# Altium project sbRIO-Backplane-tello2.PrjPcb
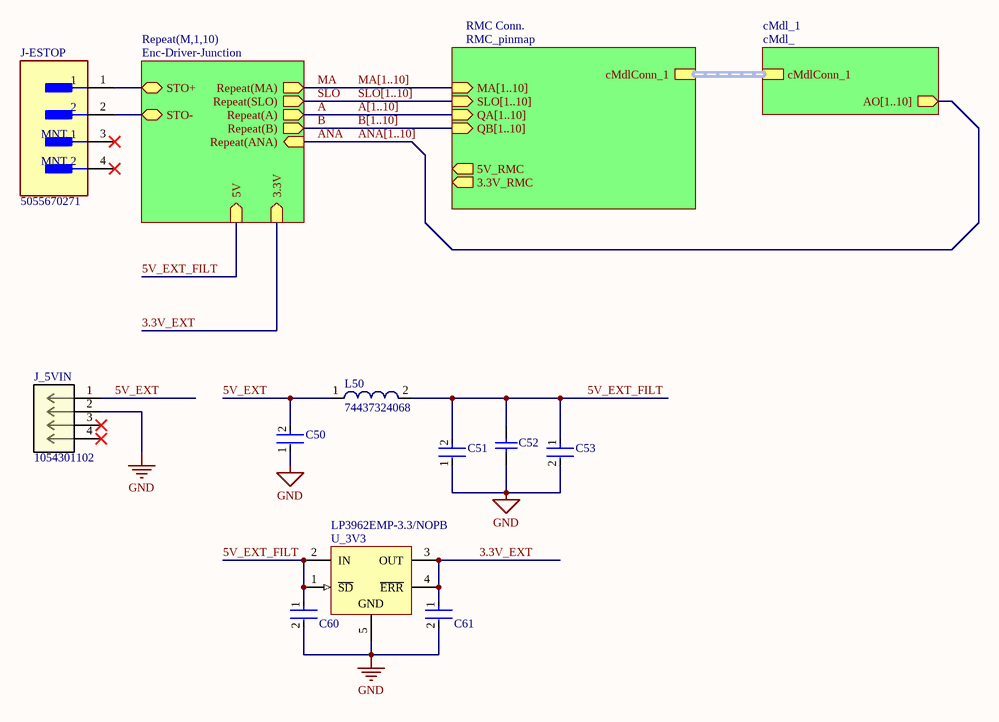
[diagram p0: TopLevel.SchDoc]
4 sheets, 123 parts. Net scope: hierarchical (ports join the sheet entries above them; power ports are global).
Board files: PCB2.PcbDoc, PCB1.PcbDoc
Sheets:
  TopLevel.SchDoc
    RMC Conn. = RMC_pinmap.SchDoc
    cMdl_1 = cMdl_.SchDoc
    M1 = Enc-Driver-Junction.SchDoc
    M2 = Enc-Driver-Junction.SchDoc
    M3 = Enc-Driver-Junction.SchDoc
    M4 = Enc-Driver-Junction.SchDoc
    M5 = Enc-Driver-Junction.SchDoc
    M6 = Enc-Driver-Junction.SchDoc
    M7 = Enc-Driver-Junction.SchDoc
    M8 = Enc-Driver-Junction.SchDoc
    M9 = Enc-Driver-Junction.SchDoc
    M10 = Enc-Driver-Junction.SchDoc

## Sheet TopLevel.SchDoc
size A; SheetNumber: 1; SheetTotal: 4

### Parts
C50  GRM155R71C104KA88D  [FP-GRM15-MFG]  (value not drawn)
C51  GRM155R71C104KA88D  [FP-GRM15-MFG]  (value not drawn)
C52  GRM31CR60J107ME39L  [CAPC3216X190X55ML30T25]  (value not drawn)
C53  0402YC103KAT2A  [FP-0402-L_1_0_1-W_0_5_0_1-MFG]  (value not drawn)
C60  C3216X5R1A686M160AC  [FP-C3216-160-0_3-MFG]  (value not drawn)
C61  C2012X5R0J336M125AC  [FP-C2012-125-0_2-IPC_C]  (value not drawn)
J-ESTOP  5055670271  [FP-5055670271-MFG]
J_5VIN  1054301102  [CON_1054301102_MOL]
L50  74437324068  [WE-LHMI 4020]
U_3V3  LP3962EMP-3.3/NOPB  [NDC0005A_M]

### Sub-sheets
cMdl_1 = cMdl_: cMdlConn_1 (harness cMdlConn_1), AO[1..10] (out)
Repeat(M,1,10) = Enc-Driver-Junction: STO- (bidir), Repeat(MA) (out), STO+ (bidir), Repeat(SLO) (out), Repeat(A) (out), Repeat(B) (out), Repeat(ANA) (in), 5V (in), 3.3V (in)
RMC Conn. = RMC_pinmap: cMdlConn_1 (harness cMdlConn_1), SLO[1..10] (in), MA[1..10] (in), QA[1..10] (in), QB[1..10] (in), 5V_RMC (out), 3.3V_RMC (out)

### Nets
GND: C50.1 C51.1 C52.1 C53.2 C60.2 C61.2 J_5VIN.2 U_3V3.5(GND)
3.3V_EXT: C61.1 U_3V3.3(OUT) U_3V3.4(~{ERR}) ; sheet Repeat(M,1,10)/3.3V
5V_EXT: C50.2 J_5VIN.1 L50.1
5V_EXT_FILT: C51.2 C52.2 C53.1 C60.1 L50.2 U_3V3.1(~{SD}) U_3V3.2(IN) ; sheet Repeat(M,1,10)/5V  [project net 5V]
STO+: J-ESTOP.1 ; sheet Repeat(M,1,10)/STO+
STO-: J-ESTOP.2 ; sheet Repeat(M,1,10)/STO-

Not connected (* = marked no-connect by the designer): J-ESTOP 3(MNT_1)* 4(MNT_2)*; J_5VIN 3* 4*

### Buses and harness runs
bus A[1..10] = sheet RMC Conn./QA[1..10]
bus ANA[1..10] = sheet cMdl_1/AO[1..10]
bus B[1..10] = sheet RMC Conn./QB[1..10]
bus MA[1..10] = sheet RMC Conn./MA[1..10]
bus SLO[1..10] = sheet RMC Conn./SLO[1..10]
harness sheet cMdl_1/cMdlConn_1 = sheet RMC Conn./cMdlConn_1

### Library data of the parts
C50 C51 = CMP-2100-03641-2: CAP CER 0.1UF 16V X7R 0402; Manufacturer: Murata; Standoff Height: 0mm; Tolerance: 10%; Voltage Rating: 16Vdc; Material: Ceramic; Capacitance: 0.10μF; Value: 0.10μF
C52 = CMP-1662-00011-2: Chip Capacitor, 100 uF, +/- 20%, 6.3 V, -55 to 85 degC, 1206 (3216 Metric), RoHS, Tape and Reel; Case\/Package: 1206; Capacitance: 100 uF; Voltage Rating (DC): 6.3 V; Type (Capacitors): X5R
C53 = CMP-2008-02797-2: General Purpose Ceramic Capacitor, 0402, 10nF, 10%, X7R, 15%, 16V; Insulation Resistance: 100GR
C60 = CMP-08246-002634-1: CAP CER 68UF 10V X5R 1206; Tolerance: 20%; Dielectric Material: Ceramic
C61 = CMP-08246-003796-1: Multilayer Ceramic Capacitors 33μF ±20% 6.3V X5R SMD 0805; Capacitance: 33uF
J-ESTOP = CMP-04776-000017-1: CONN HEADER SMD R/A 2POS 1.25MM; Manufacturer: Molex; Voltage Rating: 50V; Current Rating: 1.5A; Description: Conn Shrouded Header (4 Sides) HDR 2 POS 1.25mm Solder RA Side Entry SMD Micro-Lock™ T/R; Conn Orientation: Right Angle; Conn Gender: Male; Number Of Contacts: 2
J_5VIN = 1054301102: No Description Available; Mfr_Name: Molex Connector Corporation
L50 = CMP-1353-00039-1: SMD Power Inductor WE-LHMI, L=6.8 µH; Manufacturer: Wuerth Elektronik; Inductance: 6.8 ÂµH
U_3V3 = CMP-0062-01662-3: 1.5A Fast Ultra Low Dropout Linear Regulator, 5-pin SOT-223, Pb-Free; Manufacturer: Texas Instruments; CompType: LDO IC; PowerWise: N; PackageTopMarking: XYTT*LBEB

## Sheet RMC_pinmap.SchDoc
size A2; SheetNumber: 2; SheetTotal: 4
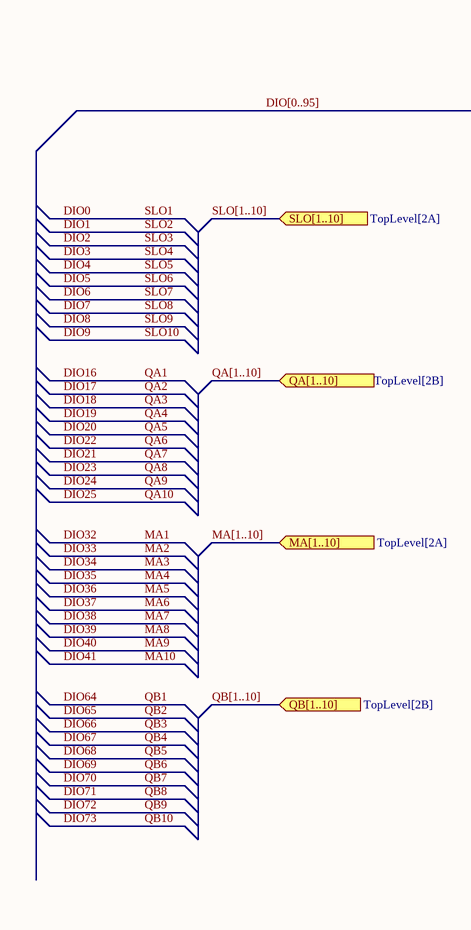
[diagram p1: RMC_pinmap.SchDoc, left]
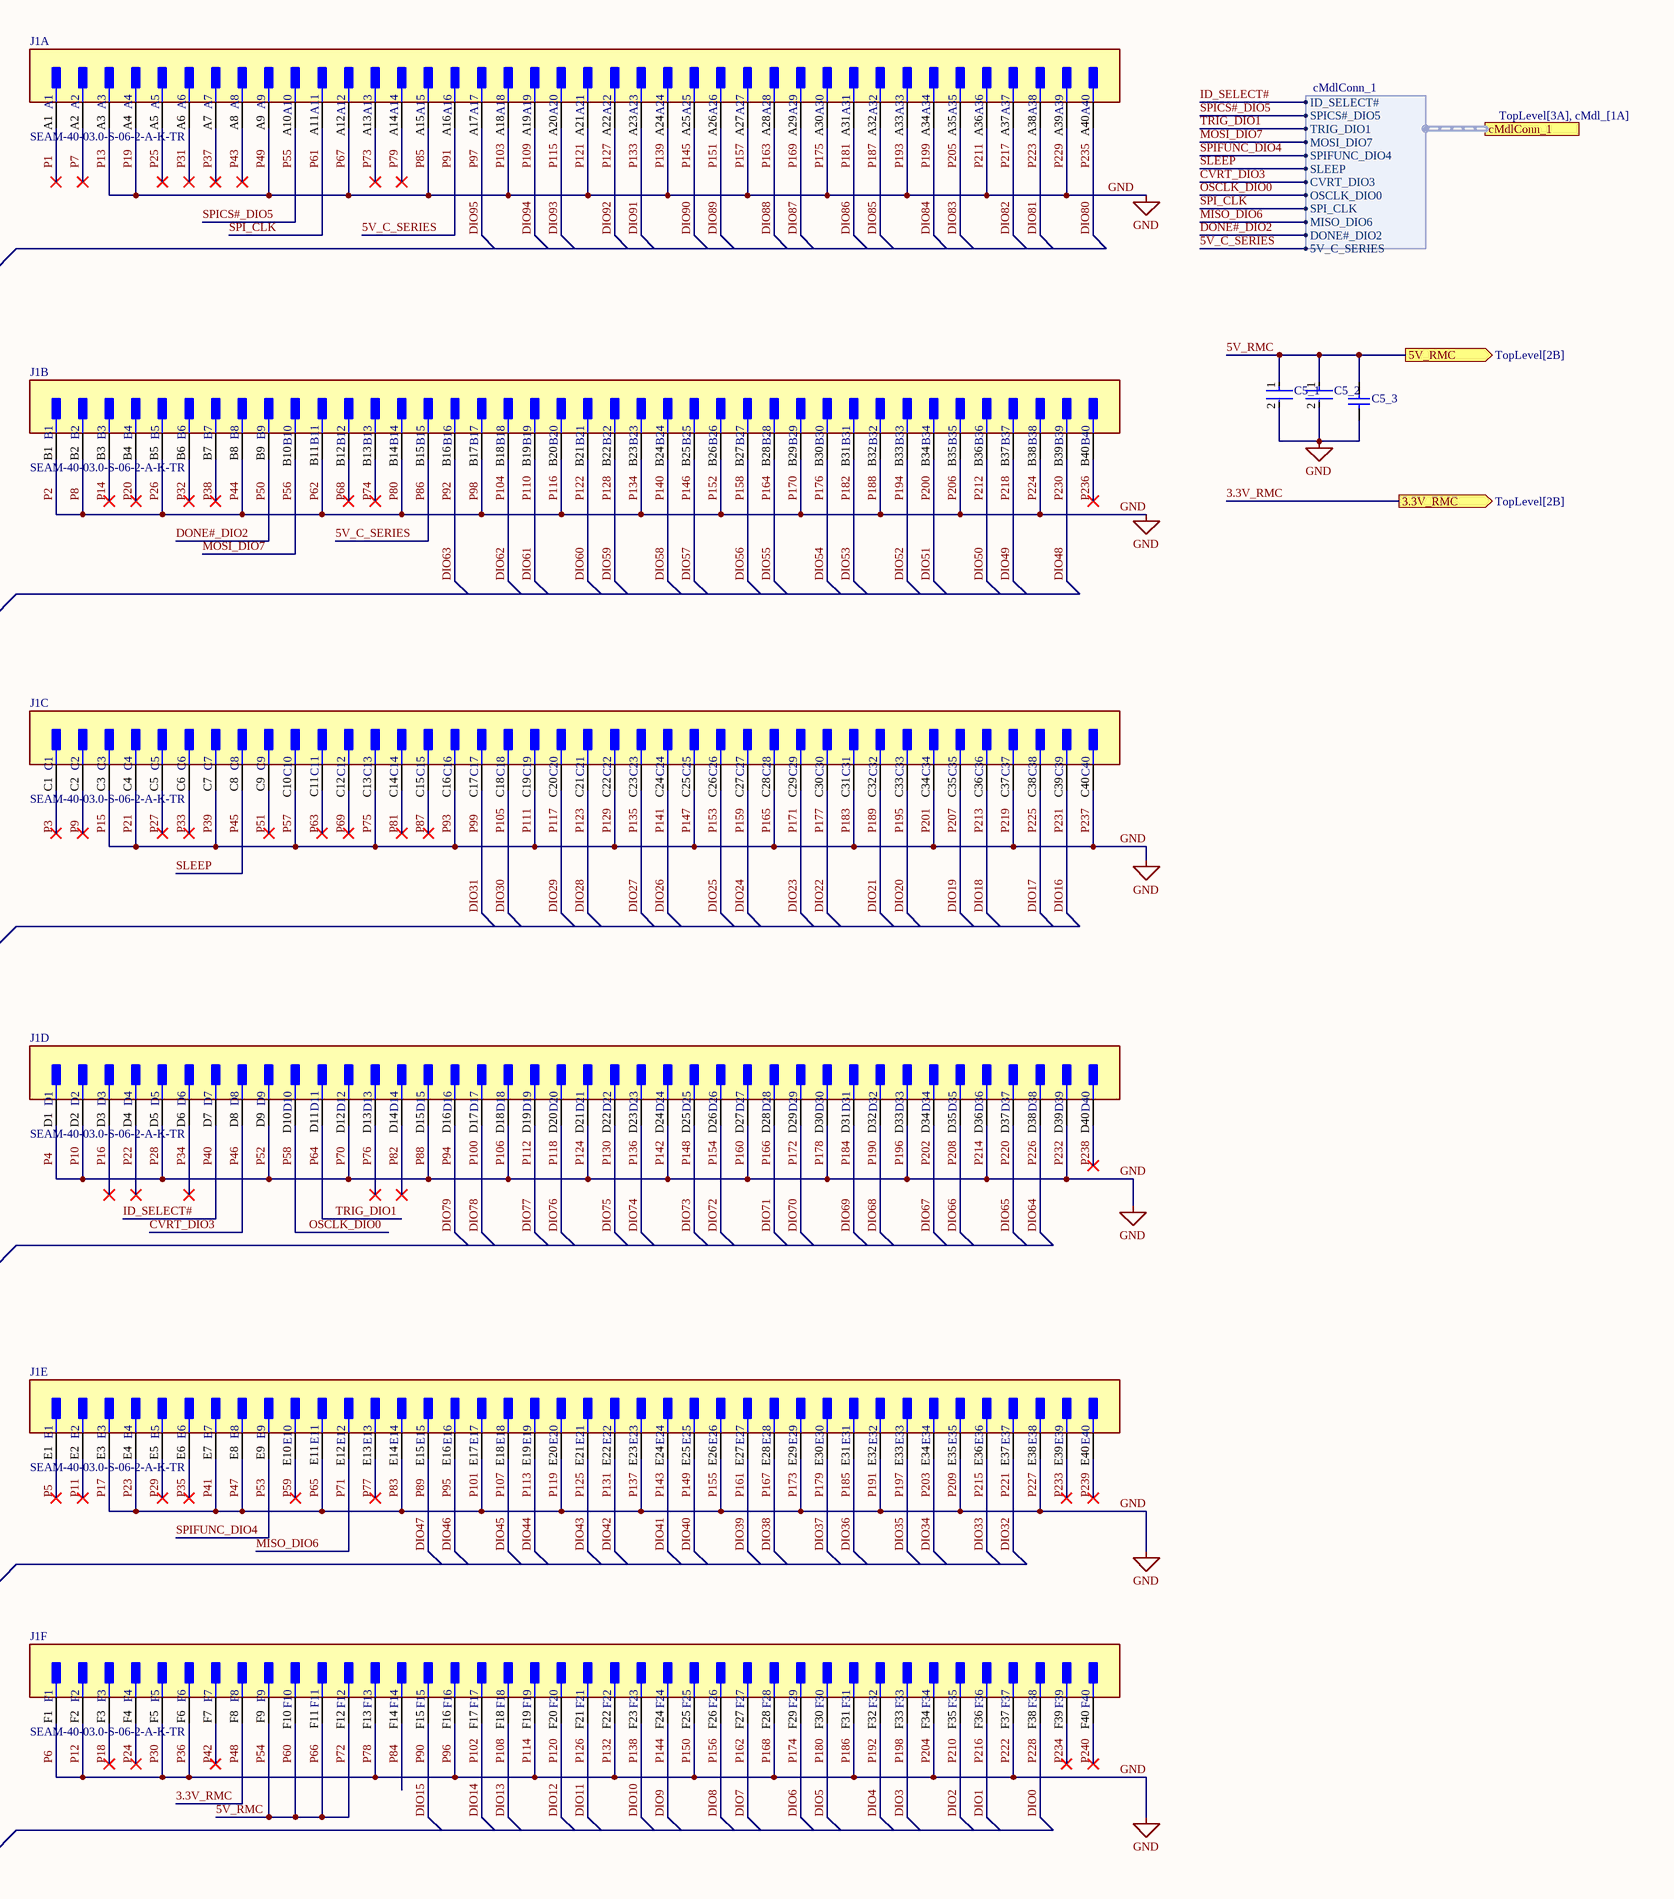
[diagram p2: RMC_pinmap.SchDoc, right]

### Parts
C5_1  C0402C105K8PACTU  [FP-C0402C105K8PACTU-MFG]  (value not drawn)
C5_2  CL05A106MP5NUNC  [FP-CL05A106MP5NUNC-MFG]  (value not drawn)
C5_3  04026D104KAT2A  [CAPC1005X56X25LL10T15]  (value not drawn)
J1  SEAM-40-03.0-S-06-2-A-K-TR  [FP-SEAM-40-03_0-S-06-2-A-MFG]  (parts A,B,C,D,E,F of 6)

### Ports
3.3V_RMC (out, see TopLevel[2B]), 5V_RMC (out, see TopLevel[2B]), cMdlConn_1 (harness cMdlConn_1, see TopLevel[3A], cMdl_[1A]), MA[1..10] (in, see TopLevel[2A]), QA[1..10] (in, see TopLevel[2B]), QB[1..10] (in, see TopLevel[2B]), SLO[1..10] (in, see TopLevel[2A])

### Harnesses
cMdlConn_1: ID_SELECT#, SPICS#_DIO5, TRIG_DIO1, MOSI_DIO7, SPIFUNC_DIO4, SLEEP, CVRT_DIO3, OSCLK_DIO0, SPI_CLK, MISO_DIO6, DONE#_DIO2, 5V_C_SERIES

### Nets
GND: C5_1.2 C5_2.2 C5_3.1 J1.A3 J1.A4 J1.A9 J1.A12 J1.A15 J1.A18 J1.A21 J1.A24 J1.A27 J1.A30 J1.A33 J1.A36 J1.A39 J1.B1 J1.B2 J1.B5 J1.B8 J1.B11 J1.B14 J1.B17 J1.B20 J1.B23 J1.B26 J1.B29 J1.B32 J1.B35 J1.B38 J1.C3 J1.C4 J1.C7 J1.C10 J1.C13 J1.C16 J1.C19 J1.C22 J1.C25 J1.C28 J1.C31 J1.C34 J1.C37 J1.C40 J1.D1 J1.D2 J1.D5 J1.D9 J1.D12 J1.D15 J1.D18 J1.D21 J1.D24 J1.D27 J1.D30 J1.D33 J1.D36 J1.D39 J1.E3 J1.E4 J1.E7 J1.E8 J1.E11 J1.E14 J1.E17 J1.E20 J1.E23 J1.E26 J1.E29 J1.E32 J1.E35 J1.E38 J1.F1 J1.F2 J1.F5 J1.F6 J1.F13 J1.F16 J1.F19 J1.F22 J1.F25 J1.F28 J1.F31 J1.F34 J1.F37  [also labelled P10, P101, P103, P106, P111, P114, P116, P119, P12, P121, P124, P129, P13, P132, P134, P137, P139, P142, P147, P15, P150, P152, P155, P157, P160, P165, P168, P17, P170, P173, P175, P178, P183, P186, P188, P19, P191, P193, P196, P2, P201, P204, P206, P209, P21, P211, P214, P219, P222, P224, P227, P229, P23, P232, P237, P26, P28, P30, P36, P39, P4, P41, P44, P47, P49, P52, P57, P6, P62, P65, P67, P70, P75, P78, P8, P80, P83, P85, P88, P93, P96, P98]
3.3V_RMC: J1.F8 ; port 3.3V_RMC  [also labelled P48]
5V_C_SERIES: J1.A16 J1.B15 ; port cMdlConn_1.5V_C_SERIES  [also labelled P86, P91]
5V_RMC: C5_1.1 C5_2.1 C5_3.2 J1.F9 J1.F10 J1.F11 J1.F12 ; port 5V_RMC  [also labelled P54, P60, P66, P72]
CVRT_DIO3: J1.D8 ; port cMdlConn_1.CVRT_DIO3  [also labelled P46]
DIO0: J1.F38  [also labelled P228, SLO1]
DIO1: J1.F36  [also labelled P216, SLO2]
DIO2: J1.F35  [also labelled P210, SLO3]
DIO3: J1.F33  [also labelled P198, SLO4]
DIO4: J1.F32  [also labelled P192, SLO5]
DIO5: J1.F30  [also labelled P180, SLO6]
DIO6: J1.F29  [also labelled P174, SLO7]
DIO7: J1.F27  [also labelled P162, SLO8]
DIO8: J1.F26  [also labelled P156, SLO9]
DIO9: J1.F24  [also labelled P144, SLO10]
DIO10: J1.F23  [also labelled P138]
DIO11: J1.F21  [also labelled P126]
DIO12: J1.F20  [also labelled P120]
DIO13: J1.F18  [also labelled P108]
DIO14: J1.F17  [also labelled P102]
DIO15: J1.F15  [also labelled P90]
DIO16: J1.C39  [also labelled P231, QA1]  [project net A]
DIO17: J1.C38  [also labelled P225, QA2]  [project net A]
DIO18: J1.C36  [also labelled P213, QA3]  [project net A]
DIO19: J1.C35  [also labelled P207, QA4]  [project net A]
DIO20: J1.C33  [also labelled P195, QA5]  [project net A]
DIO21: J1.C32  [also labelled P189, QA7]  [project net A]
DIO22: J1.C30  [also labelled P177, QA6]  [project net A]
DIO23: J1.C29  [also labelled P171, QA8]  [project net A]
DIO24: J1.C27  [also labelled P159, QA9]  [project net A]
DIO25: J1.C26  [also labelled P153, QA10]  [project net A]
DIO26: J1.C24  [also labelled P141]
DIO27: J1.C23  [also labelled P135]
DIO28: J1.C21  [also labelled P123]
DIO29: J1.C20  [also labelled P117]
DIO30: J1.C18  [also labelled P105]
DIO31: J1.C17  [also labelled P99]
DIO32: J1.E37  [also labelled MA1, P221]
DIO33: J1.E36  [also labelled MA2, P215]
DIO34: J1.E34  [also labelled MA3, P203]
DIO35: J1.E33  [also labelled MA4, P197]
DIO36: J1.E31  [also labelled MA5, P185]
DIO37: J1.E30  [also labelled MA6, P179]
DIO38: J1.E28  [also labelled MA7, P167]
DIO39: J1.E27  [also labelled MA8, P161]
DIO40: J1.E25  [also labelled MA9, P149]
DIO41: J1.E24  [also labelled MA10, P143]
DIO42: J1.E22  [also labelled P131]
DIO43: J1.E21  [also labelled P125]
DIO44: J1.E19  [also labelled P113]
DIO45: J1.E18  [also labelled P107]
DIO46: J1.E16  [also labelled P95]
DIO47: J1.E15  [also labelled P89]
DIO48: J1.B39  [also labelled P230]
DIO49: J1.B37  [also labelled P218]
DIO50: J1.B36  [also labelled P212]
DIO51: J1.B34  [also labelled P200]
DIO52: J1.B33  [also labelled P194]
DIO53: J1.B31  [also labelled P182]
DIO54: J1.B30  [also labelled P176]
DIO55: J1.B28  [also labelled P164]
DIO56: J1.B27  [also labelled P158]
DIO57: J1.B25  [also labelled P146]
DIO58: J1.B24  [also labelled P140]
DIO59: J1.B22  [also labelled P128]
DIO60: J1.B21  [also labelled P122]
DIO61: J1.B19  [also labelled P110]
DIO62: J1.B18  [also labelled P104]
DIO63: J1.B16  [also labelled P92]
DIO64: J1.D38  [also labelled P226, QB1]  [project net B]
DIO65: J1.D37  [also labelled P220, QB2]  [project net B]
DIO66: J1.D35  [also labelled P208, QB3]  [project net B]
DIO67: J1.D34  [also labelled P202, QB4]  [project net B]
DIO68: J1.D32  [also labelled P190, QB5]  [project net B]
DIO69: J1.D31  [also labelled P184, QB6]  [project net B]
DIO70: J1.D29  [also labelled P172, QB7]  [project net B]
DIO71: J1.D28  [also labelled P166, QB8]  [project net B]
DIO72: J1.D26  [also labelled P154, QB9]  [project net B]
DIO73: J1.D25  [also labelled P148, QB10]  [project net B]
DIO74: J1.D23  [also labelled P136]
DIO75: J1.D22  [also labelled P130]
DIO76: J1.D20  [also labelled P118]
DIO77: J1.D19  [also labelled P112]
DIO78: J1.D17  [also labelled P100]
DIO79: J1.D16  [also labelled P94]
DIO80: J1.A40  [also labelled P235]
DIO81: J1.A38  [also labelled P223]
DIO82: J1.A37  [also labelled P217]
DIO83: J1.A35  [also labelled P205]
DIO84: J1.A34  [also labelled P199]
DIO85: J1.A32  [also labelled P187]
DIO86: J1.A31  [also labelled P181]
DIO87: J1.A29  [also labelled P169]
DIO88: J1.A28  [also labelled P163]
DIO89: J1.A26  [also labelled P151]
DIO90: J1.A25  [also labelled P145]
DIO91: J1.A23  [also labelled P133]
DIO92: J1.A22  [also labelled P127]
DIO93: J1.A20  [also labelled P115]
DIO94: J1.A19  [also labelled P109]
DIO95: J1.A17  [also labelled P97]
DONE#_DIO2: J1.B9 ; port cMdlConn_1.DONE#_DIO2  [also labelled P50]  [project net D15_P15]
ID_SELECT#: J1.D7 ; port cMdlConn_1.ID_SELECT#  [also labelled P40]  [project net D15_P1]
MISO_DIO6: J1.E12 ; port cMdlConn_1.MISO_DIO6  [also labelled P71]  [project net D15_P12]
MOSI_DIO7: J1.B10 ; port cMdlConn_1.MOSI_DIO7  [also labelled P56]  [project net D15_P6]
OSCLK_DIO0: J1.D10 ; port cMdlConn_1.OSCLK_DIO0  [also labelled P58]  [project net D15_P10]
P1: J1.A1
P3: J1.C1
P5: J1.E1
P7: J1.A2
P9: J1.C2
P11: J1.E2
P14: J1.B3
P16: J1.D3
P18: J1.F3
P20: J1.B4
P22: J1.D4
P24: J1.F4
P25: J1.A5
P27: J1.C5
P29: J1.E5
P31: J1.A6
P32: J1.B6
P33: J1.C6
P34: J1.D6
P35: J1.E6
P37: J1.A7
P38: J1.B7
P42: J1.F7
P43: J1.A8
P45: J1.C8 ; port cMdlConn_1.SLEEP  [also labelled SLEEP]  [project net D15_P8]
P51: J1.C9
P53: J1.E9 ; port cMdlConn_1.SPIFUNC_DIO4  [also labelled SPIFUNC_DIO4]  [project net D15_P7]
P55: J1.A10 ; port cMdlConn_1.SPICS#_DIO5  [also labelled SPICS#_DIO5]  [project net D15_P2]
P59: J1.E10
P61: J1.A11 ; port cMdlConn_1.SPI_CLK  [also labelled SPI_CLK]  [project net D15_P11]
P63: J1.C11
P64: J1.D11 ; port cMdlConn_1.TRIG_DIO1  [also labelled TRIG_DIO1]  [project net D15_P5]
P68: J1.B12
P69: J1.C12
P73: J1.A13
P74: J1.B13
P76: J1.D13
P77: J1.E13
P79: J1.A14
P81: J1.C14
P82: J1.D14
P84: J1.F14
P87: J1.C15
P233: J1.E39
P234: J1.F39
P236: J1.B40
P238: J1.D40
P239: J1.E40
P240: J1.F40

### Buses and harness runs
bus DIO[0..95]
bus MA[1..10] = port MA[1..10]
bus QA[1..10] = port QA[1..10]
bus QB[1..10] = port QB[1..10]
bus SLO[1..10] = port SLO[1..10]

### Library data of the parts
C5_1 = CMP-2008-02081-2: CAP CER 1UF 10V X5R 0402; Dielectric Material: Ceramic; Dissipation Factor: 5%; Tolerance: 10%
C5_2 = CMP-13271-000002-1: CAP CER 10UF 10V X5R 0402; Manufacturer: Samsung; Temperature Coefficient: 15%; Tolerance: 20%; Description: Cap Ceramic 10uF 10V X5R 20% SMD 0402 85C T/R; Material: Ceramic
C5_3 = CMP-2008-02743-1: Manufacturer: AVX Interconnect / Elco
J1 = CMP-02761-000136-1: CONN HD ARRAY PLUG 240P SMD GOLD; Max Current Rating: 2.3A; Contact Resistance: 5.5mR; Number of Contacts: 240; Pitch: 1.27mm; Gender: Male; Max Voltage Rating (AC): 240V

## Sheet cMdl_.SchDoc
size A; SheetNumber: 3; SheetTotal: 4
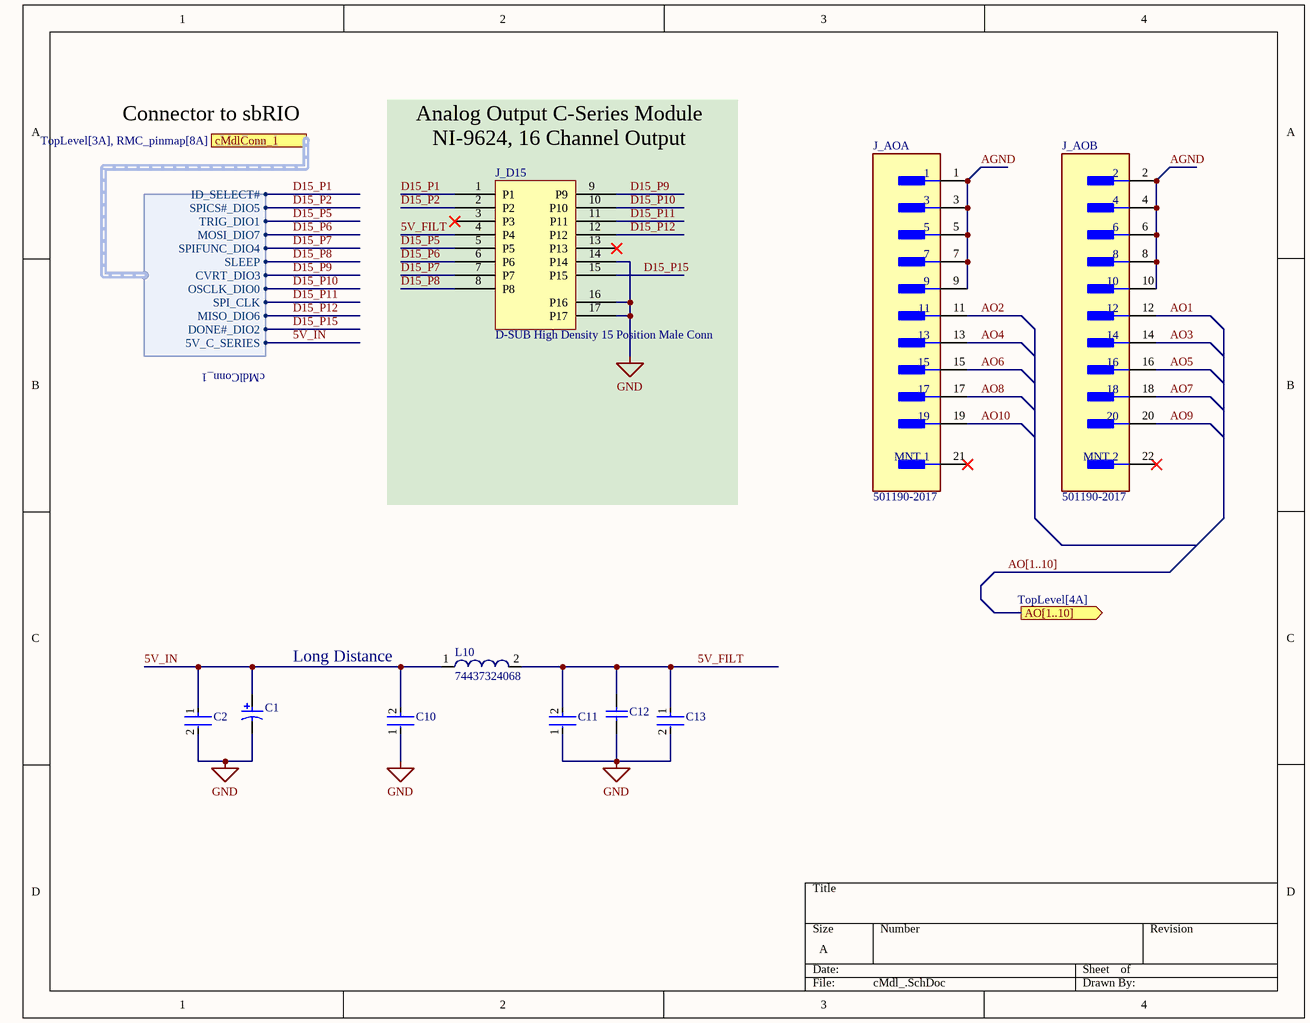
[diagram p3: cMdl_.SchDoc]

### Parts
C1  TPSD337K006R0050  [CAPMP7344X31-T_V]  (value not drawn)
C2  GRM155R60J475ME47D  [FP-GRM155-0_1-IPC_B]  (value not drawn)
C10  GRM155R71C104KA88D  [FP-GRM15-MFG]  (value not drawn)
C11  GRM155R71C104KA88D  [FP-GRM15-MFG]  (value not drawn)
C12  GRM31CR60J107ME39L  [CAPC3216X190X55ML30T25]  (value not drawn)
C13  0402YC103KAT2A  [FP-0402-L_1_0_1-W_0_5_0_1-MFG]  (value not drawn)
J_AO  501190-2017  [FP-501190-2017-MFG]  (parts A,B of 2)
J_D15  D-SUB High Density 15 Position Male Conn  [D-SUB High Density 15 Position Male Conn-Footprint-1]
L10  74437324068  [WE-LHMI 4020]

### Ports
AO[1..10] (out, see TopLevel[4A]), cMdlConn_1 (harness cMdlConn_1, see TopLevel[3A], RMC_pinmap[8A])

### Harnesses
cMdlConn_1: 5V_C_SERIES, CVRT_DIO3, DONE#_DIO2, ID_SELECT#, MISO_DIO6, MOSI_DIO7, OSCLK_DIO0, SLEEP, SPICS#_DIO5, SPIFUNC_DIO4, SPI_CLK, TRIG_DIO1

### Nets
GND: C1.2 C2.2 C10.1 C11.1 C12.1 C13.2 J_D15.14(P14) J_D15.16(P16) J_D15.17(P17)
5V_FILT: C11.2 C12.2 C13.1 J_D15.4(P4) L10.2
5V_IN: C1.1 C2.1 C10.2 L10.1 ; port cMdlConn_1.5V_C_SERIES  [project net 5V_C_SERIES]
AGND: J_AO.1 J_AO.2 J_AO.3 J_AO.4 J_AO.5 J_AO.6 J_AO.7 J_AO.8 J_AO.9 J_AO.10
AO1: J_AO.12  [project net ANA]
AO2: J_AO.11  [project net ANA]
AO3: J_AO.14  [project net ANA]
AO4: J_AO.13  [project net ANA]
AO5: J_AO.16  [project net ANA]
AO6: J_AO.15  [project net ANA]
AO7: J_AO.18  [project net ANA]
AO8: J_AO.17  [project net ANA]
AO9: J_AO.20  [project net ANA]
AO10: J_AO.19  [project net ANA]
D15_P1: J_D15.1(P1) ; port cMdlConn_1.ID_SELECT#
D15_P2: J_D15.2(P2) ; port cMdlConn_1.SPICS#_DIO5
D15_P5: J_D15.5(P5) ; port cMdlConn_1.TRIG_DIO1
D15_P6: J_D15.6(P6) ; port cMdlConn_1.MOSI_DIO7
D15_P7: J_D15.7(P7) ; port cMdlConn_1.SPIFUNC_DIO4
D15_P8: J_D15.8(P8) ; port cMdlConn_1.SLEEP
D15_P9: J_D15.9(P9) ; port cMdlConn_1.CVRT_DIO3  [project net CVRT_DIO3]
D15_P10: J_D15.10(P10) ; port cMdlConn_1.OSCLK_DIO0
D15_P11: J_D15.11(P11) ; port cMdlConn_1.SPI_CLK
D15_P12: J_D15.12(P12) ; port cMdlConn_1.MISO_DIO6
D15_P15: J_D15.15(P15) ; port cMdlConn_1.DONE#_DIO2

Not connected (* = marked no-connect by the designer): J_AO 21(MNT_1)* 22(MNT_2)*; J_D15 3(P3)* 13(P13)*

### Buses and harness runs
bus AO[1..10] = port AO[1..10]

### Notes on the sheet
- Connector to sbRIO
- (near J_D15) Analog Output C-Series Module
  NI-9624, 16 Channel Output
- Long Distance

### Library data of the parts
C1 = CMP-2000-07305-1: Low ESR, 330 uF, 6.3 V, +/- 10%, -55 to 125 degC, 2-Pin SMD, RoHS, Tape and Reel; Manufacturer: AVX; Rad Hardened: No; DF: 8%; Capacitance: 330000000pF; Product Depth (mm): 4.3mm; Wire Form: NotRequired; Lead Spacing (nom): NotRequiredmm; Case Style: Molded; Product Length (mm): 7.3mm; Voltage: 6.3VDC; DCL: 20.8uA; ESR: 0.05ohm; Product Height (mm): 2.9mm; Polarity: Polar
C2 = CMP-2008-04549-2: Chip Multilayer Ceramic Capacitors for General Purpose, 0402, 4.7uF, X5R, 15%, 20%, 6.3V
C10 C11 = CMP-2100-03641-2: as C50 on sheet TopLevel
C12 = CMP-1662-00011-2: as C52 on sheet TopLevel
C13 = CMP-2008-02797-2: as C53 on sheet TopLevel
J_AO = CMP-04776-000294-1: CONN HEADER SMD 20POS 1MM; Contact Resistance: 20mR; Number of Contacts: 20; Voltage Rating: 50V; Connector Type: Male Pin; Current Rating: 1A; Glow Wire Compliant: Non-compliant; Row Spacing: 0.105inch; Gender: Male
J_D15 = D-Sub 15 Male-2
L10 = CMP-1353-00039-1: as L50 on sheet TopLevel

## Sheet Enc-Driver-Junction.SchDoc
size A; SheetNumber: 4; SheetTotal: 4
Used 10 times, as channels M1, M2, M3, M4, M5, M6, M7, M8, M9, M10. Parts and nets are listed once, with the designators drawn on the sheet.
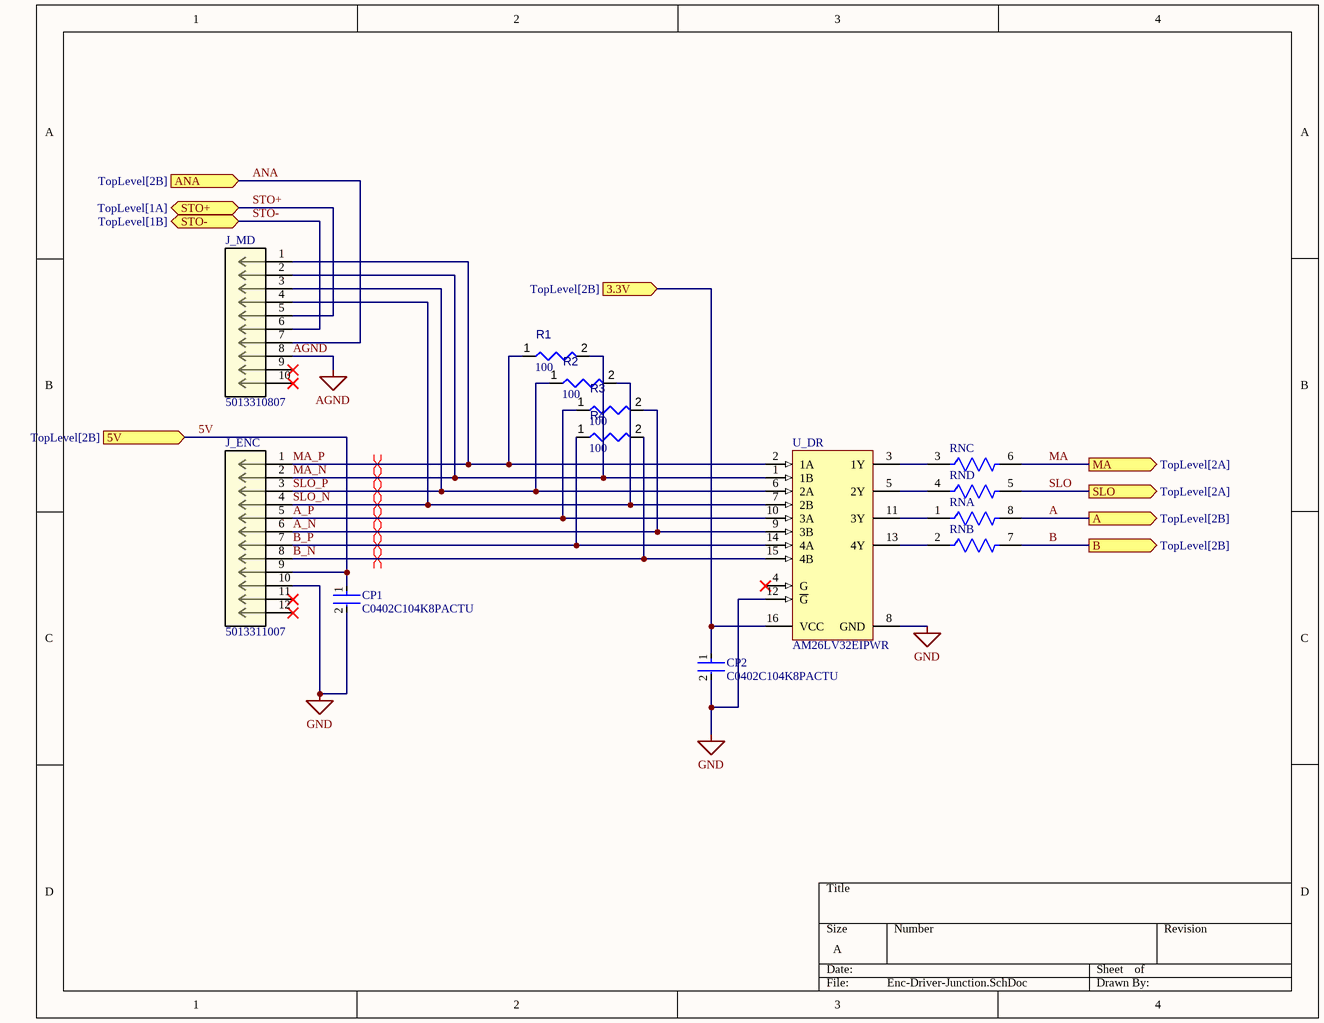
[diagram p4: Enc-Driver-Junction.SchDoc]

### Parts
CP1  C0402C104K8PACTU  [FP-C0402-BB-MFG]
CP2  C0402C104K8PACTU  [FP-C0402-BB-MFG]
J_ENC  5013311007  [PicoClasp_Rcpt_10Pos_Vert]
J_MD  5013310807  [CON_5013310807]
R1  value 100  [RESC0402(1005)_L]  (hidden comment: Resistor 100R +/-1 % 0402 63 mW)
R2  value 100  [RESC0402(1005)_L]  (hidden comment: Resistor 100R +/-1 % 0402 63 mW)
R3  value 100  [RESC0402(1005)_L]  (hidden comment: Resistor 100R +/-1 % 0402 63 mW)
R4  value 100  [RESC0402(1005)_L]  (hidden comment: Resistor 100R +/-1 % 0402 63 mW)
RN  742C083470JP  [FP-742C083-MFG]  (value not drawn)  (parts A,B,C,D of 4)
U_DR  AM26LV32EIPWR  [PW0016A_L]

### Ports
3.3V (in, see TopLevel[2B]), 5V (in, see TopLevel[2B]), A (out, see TopLevel[2B]), ANA (in, see TopLevel[2B]), B (out, see TopLevel[2B]), MA (out, see TopLevel[2A]), SLO (out, see TopLevel[2A]), STO+ (bidir, see TopLevel[1A]), STO- (bidir, see TopLevel[1B])

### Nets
AGND: J_MD.8
GND: CP1.2 CP2.2 J_ENC.10 U_DR.8(GND) U_DR.12(~{G})
3.3V: CP2.1 U_DR.16(VCC) ; port 3.3V
5V: CP1.1 J_ENC.9 ; port 5V
A: RN.8 ; port A
A_N: J_ENC.6 R3.2 U_DR.9(3B)
A_P: J_ENC.5 R3.1 U_DR.10(3A)
ANA: J_MD.7 ; port ANA
B: RN.7 ; port B
B_N: J_ENC.8 R4.2 U_DR.15(4B)
B_P: J_ENC.7 R4.1 U_DR.14(4A)
MA: RN.6 ; port MA
MA_N: J_ENC.2 J_MD.2 R1.2 U_DR.1(1B)
MA_P: J_ENC.1 J_MD.1 R1.1 U_DR.2(1A)
SLO: RN.5 ; port SLO
SLO_N: J_ENC.4 J_MD.4 R2.2 U_DR.7(2B)
SLO_P: J_ENC.3 J_MD.3 R2.1 U_DR.6(2A)
STO+: J_MD.5 ; port STO+
STO-: J_MD.6 ; port STO-
NetRN_1: RN.1 U_DR.11(3Y)
NetRN_2: RN.2 U_DR.13(4Y)
NetRN_3: RN.3 U_DR.3(1Y)
NetRN_4: RN.4 U_DR.5(2Y)

Not connected (* = marked no-connect by the designer): J_ENC 11* 12*; J_MD 9* 10*; U_DR 4(G)*

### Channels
M1: designators end in _M1; ports 3.3V=3.3V_EXT 5V=5V A=A ANA=ANA B=B MA=DIO32 SLO=DIO0 STO+=STO+ STO-=STO-
M2: designators end in _M2; ports 3.3V=3.3V_EXT 5V=5V A=A ANA=ANA B=B MA=DIO33 SLO=DIO1 STO+=STO+ STO-=STO-
M3: designators end in _M3; ports 3.3V=3.3V_EXT 5V=5V A=A ANA=ANA B=B MA=DIO34 SLO=DIO2 STO+=STO+ STO-=STO-
M4: designators end in _M4; ports 3.3V=3.3V_EXT 5V=5V A=A ANA=ANA B=B MA=DIO35 SLO=DIO3 STO+=STO+ STO-=STO-
M5: designators end in _M5; ports 3.3V=3.3V_EXT 5V=5V A=A ANA=ANA B=B MA=DIO36 SLO=DIO4 STO+=STO+ STO-=STO-
M6: designators end in _M6; ports 3.3V=3.3V_EXT 5V=5V A=A ANA=ANA B=B MA=DIO37 SLO=DIO5 STO+=STO+ STO-=STO-
M7: designators end in _M7; ports 3.3V=3.3V_EXT 5V=5V A=A ANA=ANA B=B MA=DIO38 SLO=DIO6 STO+=STO+ STO-=STO-
M8: designators end in _M8; ports 3.3V=3.3V_EXT 5V=5V A=A ANA=ANA B=B MA=DIO39 SLO=DIO7 STO+=STO+ STO-=STO-
M9: designators end in _M9; ports 3.3V=3.3V_EXT 5V=5V A=A ANA=ANA B=B MA=DIO40 SLO=DIO8 STO+=STO+ STO-=STO-
M10: designators end in _M10; ports 3.3V=3.3V_EXT 5V=5V A=A ANA=ANA B=B MA=DIO41 SLO=DIO9 STO+=STO+ STO-=STO-

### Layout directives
differential pair: A_N_M1, A_P_M1, B_N_M1, B_P_M1, MA_N_M1, MA_P_M1, SLO_N_M1, SLO_P_M1

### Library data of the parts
CP1 CP2 = CMP-2008-02046-2: CAP CER 0.1UF 10V X5R 0402; Manufacturer: Kemet; Capacitance: 0.10 μF; Temperature Coefficient: 15%; Tolerance: 0.1; Value: 0.10 μF
J_ENC = CMP-003-000001-2: No Description Available; Mfr_Name: Molex Connector Corporation
J_MD = CMP-005-000000-1: No Description Available; Mfr_Name: Molex Connector Corporation
R1-R4 = CMP-009-00167-3: Chip Resistor, 100 Ohms, +/-1 %, 63 mW, -55 to 155 degC, 0402; Power: 63mW; Tolerance: 1%
RN = CMP-06828-000004-1: RES ARRAY 4 RES 47 OHM 1206; Number of Elements: 4; Resistance: 47R; Circuit Type: Isolated; Temperature Coefficient: 200ppm/°C; Power Dissipation: 63mW; Tolerance: 5%; Working Voltage: 50V
U_DR = CMP-0310-00537-3: Low-Voltage High-Speed Quadruple Differential Line Receiver with +/-15-kV IEC ESD, 0 TX / 4 RX, 3.3V, -40 to 85 degC, 16-Pin TSSOP (PW), Green(RoHS & no Sb/Br); Manufacturer: Texas Instruments; Supply Voltage(s)(Min)(V): 3; Supply Voltage(s)(Max)(V): 3.6; Receivers Per Package: 4; SubFamily: RS-422; ESD(kV): 15; Supply Voltage(s)(V): 3.3; Rating: Catalog

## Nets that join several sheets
AGND: M1 (J_MD_M1.8), M2 (J_MD_M2.8), M3 (J_MD_M3.8), M4 (J_MD_M4.8), M5 (J_MD_M5.8), M6 (J_MD_M6.8), M7 (J_MD_M7.8), M8 (J_MD_M8.8), M9 (J_MD_M9.8), M10 (J_MD_M10.8)
GND: TopLevel (8 pins), RMC_pinmap (85 pins), cMdl_ (9 pins), M1 (5 pins), M2 (5 pins), M3 (5 pins), M4 (5 pins), M5 (5 pins), M6 (5 pins), M7 (5 pins), M8 (5 pins), M9 (5 pins), M10 (5 pins)
3.3V_EXT: TopLevel (C61.1 U_3V3.3 U_3V3.4), M1 (CP2_M1.1 U_DR_M1.16), M2 (CP2_M2.1 U_DR_M2.16), M3 (CP2_M3.1 U_DR_M3.16), M4 (CP2_M4.1 U_DR_M4.16), M5 (CP2_M5.1 U_DR_M5.16), M6 (CP2_M6.1 U_DR_M6.16), M7 (CP2_M7.1 U_DR_M7.16), M8 (CP2_M8.1 U_DR_M8.16), M9 (CP2_M9.1 U_DR_M9.16), M10 (CP2_M10.1 U_DR_M10.16)
5V: TopLevel (7 pins), M1 (CP1_M1.1 J_ENC_M1.9), M2 (CP1_M2.1 J_ENC_M2.9), M3 (CP1_M3.1 J_ENC_M3.9), M4 (CP1_M4.1 J_ENC_M4.9), M5 (CP1_M5.1 J_ENC_M5.9), M6 (CP1_M6.1 J_ENC_M6.9), M7 (CP1_M7.1 J_ENC_M7.9), M8 (CP1_M8.1 J_ENC_M8.9), M9 (CP1_M9.1 J_ENC_M9.9), M10 (CP1_M10.1 J_ENC_M10.9)
5V_C_SERIES: RMC_pinmap (J1.A16 J1.B15), cMdl_ (C1.1 C2.1 C10.2 L10.1)
A: RMC_pinmap (J1.C26), M10 (RN_M10.8)
A: RMC_pinmap (J1.C27), M9 (RN_M9.8)
A: RMC_pinmap (J1.C29), M8 (RN_M8.8)
A: RMC_pinmap (J1.C30), M6 (RN_M6.8)
A: RMC_pinmap (J1.C32), M7 (RN_M7.8)
A: RMC_pinmap (J1.C33), M5 (RN_M5.8)
A: RMC_pinmap (J1.C35), M4 (RN_M4.8)
A: RMC_pinmap (J1.C36), M3 (RN_M3.8)
A: RMC_pinmap (J1.C38), M2 (RN_M2.8)
A: RMC_pinmap (J1.C39), M1 (RN_M1.8)
ANA: cMdl_ (J_AO.11), M2 (J_MD_M2.7)
ANA: cMdl_ (J_AO.13), M4 (J_MD_M4.7)
ANA: cMdl_ (J_AO.15), M6 (J_MD_M6.7)
ANA: cMdl_ (J_AO.17), M8 (J_MD_M8.7)
ANA: cMdl_ (J_AO.19), M10 (J_MD_M10.7)
ANA: cMdl_ (J_AO.12), M1 (J_MD_M1.7)
ANA: cMdl_ (J_AO.14), M3 (J_MD_M3.7)
ANA: cMdl_ (J_AO.16), M5 (J_MD_M5.7)
ANA: cMdl_ (J_AO.18), M7 (J_MD_M7.7)
ANA: cMdl_ (J_AO.20), M9 (J_MD_M9.7)
B: RMC_pinmap (J1.D25), M10 (RN_M10.7)
B: RMC_pinmap (J1.D26), M9 (RN_M9.7)
B: RMC_pinmap (J1.D28), M8 (RN_M8.7)
B: RMC_pinmap (J1.D29), M7 (RN_M7.7)
B: RMC_pinmap (J1.D31), M6 (RN_M6.7)
B: RMC_pinmap (J1.D32), M5 (RN_M5.7)
B: RMC_pinmap (J1.D34), M4 (RN_M4.7)
B: RMC_pinmap (J1.D35), M3 (RN_M3.7)
B: RMC_pinmap (J1.D37), M2 (RN_M2.7)
B: RMC_pinmap (J1.D38), M1 (RN_M1.7)
CVRT_DIO3: RMC_pinmap (J1.D8), cMdl_ (J_D15.9)
D15_P1: RMC_pinmap (J1.D7), cMdl_ (J_D15.1)
D15_P2: RMC_pinmap (J1.A10), cMdl_ (J_D15.2)
D15_P5: RMC_pinmap (J1.D11), cMdl_ (J_D15.5)
D15_P6: RMC_pinmap (J1.B10), cMdl_ (J_D15.6)
D15_P7: RMC_pinmap (J1.E9), cMdl_ (J_D15.7)
D15_P8: RMC_pinmap (J1.C8), cMdl_ (J_D15.8)
D15_P10: RMC_pinmap (J1.D10), cMdl_ (J_D15.10)
D15_P11: RMC_pinmap (J1.A11), cMdl_ (J_D15.11)
D15_P12: RMC_pinmap (J1.E12), cMdl_ (J_D15.12)
D15_P15: RMC_pinmap (J1.B9), cMdl_ (J_D15.15)
DIO0: RMC_pinmap (J1.F38), M1 (RN_M1.5)
DIO1: RMC_pinmap (J1.F36), M2 (RN_M2.5)
DIO2: RMC_pinmap (J1.F35), M3 (RN_M3.5)
DIO3: RMC_pinmap (J1.F33), M4 (RN_M4.5)
DIO4: RMC_pinmap (J1.F32), M5 (RN_M5.5)
DIO5: RMC_pinmap (J1.F30), M6 (RN_M6.5)
DIO6: RMC_pinmap (J1.F29), M7 (RN_M7.5)
DIO7: RMC_pinmap (J1.F27), M8 (RN_M8.5)
DIO8: RMC_pinmap (J1.F26), M9 (RN_M9.5)
DIO9: RMC_pinmap (J1.F24), M10 (RN_M10.5)
DIO32: RMC_pinmap (J1.E37), M1 (RN_M1.6)
DIO33: RMC_pinmap (J1.E36), M2 (RN_M2.6)
DIO34: RMC_pinmap (J1.E34), M3 (RN_M3.6)
DIO35: RMC_pinmap (J1.E33), M4 (RN_M4.6)
DIO36: RMC_pinmap (J1.E31), M5 (RN_M5.6)
DIO37: RMC_pinmap (J1.E30), M6 (RN_M6.6)
DIO38: RMC_pinmap (J1.E28), M7 (RN_M7.6)
DIO39: RMC_pinmap (J1.E27), M8 (RN_M8.6)
DIO40: RMC_pinmap (J1.E25), M9 (RN_M9.6)
DIO41: RMC_pinmap (J1.E24), M10 (RN_M10.6)
STO+: TopLevel (J-ESTOP.1), M1 (J_MD_M1.5), M2 (J_MD_M2.5), M3 (J_MD_M3.5), M4 (J_MD_M4.5), M5 (J_MD_M5.5), M6 (J_MD_M6.5), M7 (J_MD_M7.5), M8 (J_MD_M8.5), M9 (J_MD_M9.5), M10 (J_MD_M10.5)
STO-: TopLevel (J-ESTOP.2), M1 (J_MD_M1.6), M2 (J_MD_M2.6), M3 (J_MD_M3.6), M4 (J_MD_M4.6), M5 (J_MD_M5.6), M6 (J_MD_M6.6), M7 (J_MD_M7.6), M8 (J_MD_M8.6), M9 (J_MD_M9.6), M10 (J_MD_M10.6)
